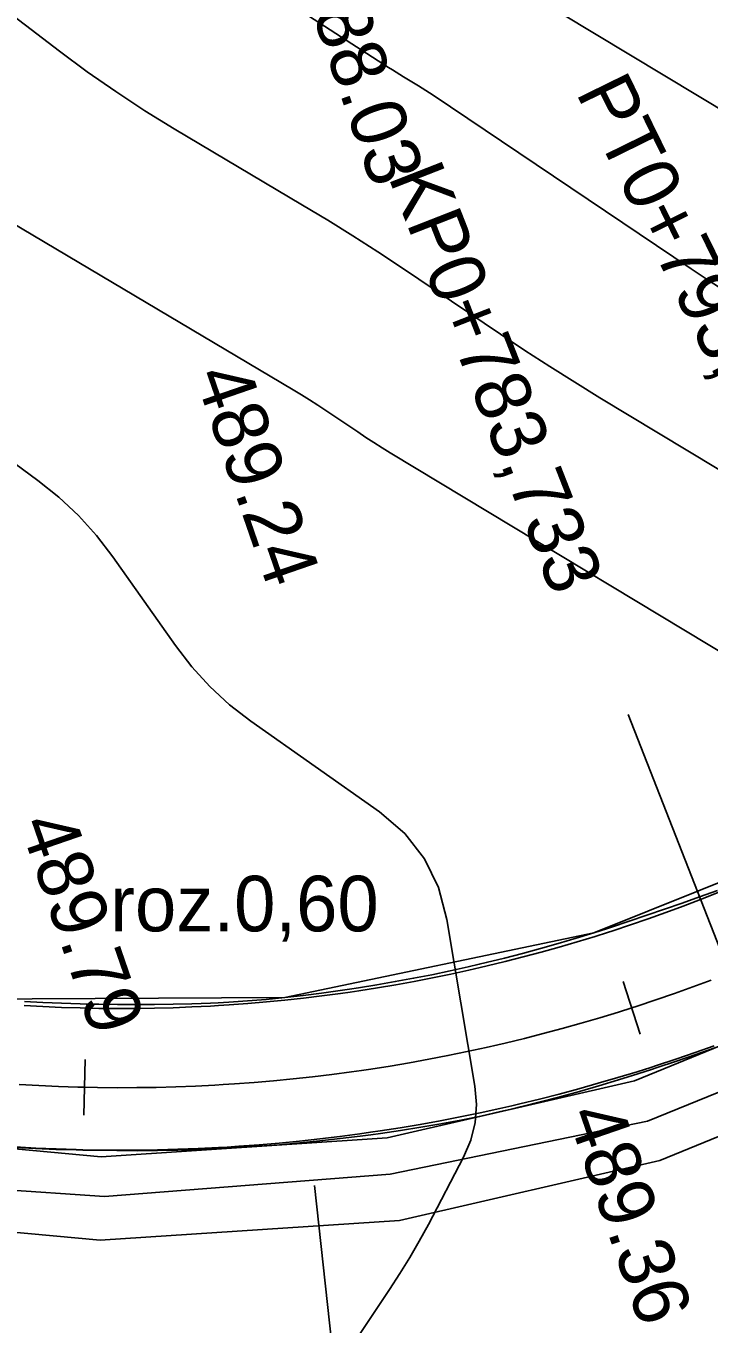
# Model space of a CAD drawing. Extents: x -636600 to -628587, y -1090963 to -1085869.
# Drawn here: x -629074.47 to -629049.89, y -1090800.23 to -1090753.51 of the extents above; entities that cross this region are included whole.
import ezdxf

# ---------------------------------------------------------------- set-up
doc = ezdxf.new("R2010")
doc.units = 0
for name, color, linetype in [('01_PARCELY_NÁVRH_PC', 7, 'Continuous'), ('06_ÚSES_IP_NAVRH', 7, 'Continuous'), ('Ex_Major Contours', 7, 'Continuous'), ('Ex_Minor Contours', 7, 'Continuous'), ('HEKTOMETRY20', 7, 'Continuous'), ('HL_BODY', 7, 'Continuous'), ('koty_vše', 7, 'Continuous'), ('popis', 7, 'Continuous'), ('situace_osa', 7, 'Continuous'), ('situace_těleso', 7, 'Continuous'), ('situace_vozovka', 7, 'Continuous'), ('VRCHOLY', 7, 'Continuous')]:
    doc.layers.add(name, color=color, linetype=linetype)

msp = doc.modelspace()

# ---------------------------------------------------------------- linework, layer by layer
at = {"layer": '01_PARCELY_NÁVRH_PC'}
for points in [[(-629333.446, -1090807.798), (-629185.545, -1090774.978), (-629169.22, -1090774.091), (-629152.689, -1090776.12), (-629083.293, -1090793.147), (-629071.767, -1090794.209), (-629061.471, -1090793.529), (-629052.567, -1090791.475), (-629024.023, -1090779.799), (-629026.589, -1090772.578), (-629040.908, -1090778.632), (-629044.438, -1090782.302), (-629054.034, -1090786.148), (-629065.163, -1090788.479), (-629076.541, -1090788.542), (-629088.985, -1090786.736), (-629149.055, -1090771.958), (-629163.015, -1090769.651), (-629176.084, -1090769.189), (-629189.661, -1090770.446), (-629215.418, -1090775.798)], [(-629332.923, -1090810.755), (-629185.135, -1090777.96), (-629169.323, -1090777.101), (-629153.231, -1090779.076), (-629083.791, -1090796.114), (-629071.806, -1090797.219), (-629061.032, -1090796.507), (-629051.656, -1090794.344), (-629022.513, -1090782.423), (-629023.82, -1090780.369), (-629024.023, -1090779.799), (-629052.567, -1090791.475), (-629061.471, -1090793.529), (-629071.767, -1090794.209), (-629083.293, -1090793.147), (-629152.689, -1090776.12), (-629169.22, -1090774.091), (-629185.545, -1090774.978), (-629333.446, -1090807.798)]]:
    msp.add_lwpolyline(points, dxfattribs=at)
at = {"layer": '06_ÚSES_IP_NAVRH'}
msp.add_lwpolyline([(-629532.12, -1090817.987), (-629446.562, -1090815.158), (-629358.786, -1090812.637), (-629333.428, -1090809.41), (-629185.496, -1090776.496), (-629168.602, -1090775.784), (-629152.436, -1090777.592), (-629083.514, -1090794.829), (-629071.645, -1090795.644), (-629061.361, -1090794.844), (-629052.102, -1090792.936), (-629028.219, -1090783.132)], dxfattribs=at)
at = {"layer": 'Ex_Major Contours'}
msp.add_lwpolyline([(-629056.478, -1090752.283), (-629044.065, -1090759.768)], dxfattribs=at)
at = {"layer": 'Ex_Minor Contours'}
for points in [[(-629049.305, -1090763.06), (-629049.923, -1090762.66), (-629050.536, -1090762.253), (-629059.817, -1090756.004), (-629059.948, -1090755.917), (-629060.08, -1090755.831), (-629060.213, -1090755.748), (-629060.347, -1090755.666), (-629060.887, -1090755.34), (-629061.021, -1090755.259), (-629061.155, -1090755.176), (-629061.288, -1090755.092), (-629061.421, -1090755.007), (-629079.382, -1090743.406)], [(-629082.651, -1090747.242), (-629073.269, -1090754.42), (-629072.267, -1090755.164), (-629071.244, -1090755.878), (-629070.2, -1090756.562), (-629069.136, -1090757.215), (-629064.52, -1090759.958), (-629063.61, -1090760.508), (-629062.708, -1090761.07), (-629061.814, -1090761.644), (-629060.928, -1090762.232), (-629057.4, -1090764.607), (-629056.514, -1090765.196), (-629055.622, -1090765.773), (-629054.722, -1090766.338), (-629053.815, -1090766.893), (-629046.428, -1090771.345)], [(-629046.352, -1090777.92), (-629061.363, -1090768.873), (-629061.659, -1090768.692), (-629061.953, -1090768.507), (-629062.244, -1090768.319), (-629062.533, -1090768.127), (-629063.683, -1090767.353), (-629063.972, -1090767.161), (-629064.264, -1090766.973), (-629064.558, -1090766.79), (-629064.855, -1090766.611), (-629078.698, -1090758.386)], [(-629085.748, -1090761.24), (-629074.048, -1090769.87), (-629073.29, -1090770.476), (-629072.587, -1090771.137), (-629071.941, -1090771.853), (-629071.349, -1090772.623), (-629069.096, -1090775.813), (-629068.503, -1090776.581), (-629067.852, -1090777.29), (-629067.143, -1090777.942), (-629066.375, -1090778.535), (-629061.755, -1090781.801), (-629060.844, -1090782.58), (-629060.135, -1090783.486), (-629059.627, -1090784.519), (-629059.322, -1090785.678), (-629058.32, -1090791.667), (-629058.26, -1090792.332), (-629058.309, -1090792.98), (-629058.464, -1090793.611), (-629058.727, -1090794.225), (-629059.992, -1090796.646), (-629060.317, -1090797.246), (-629060.657, -1090797.838), (-629061.013, -1090798.419), (-629061.385, -1090798.991), (-629064.839, -1090804.149)]]:
    msp.add_lwpolyline(points, dxfattribs=at)
at = {"layer": 'HEKTOMETRY20'}
for points in [[(-629052.976, -1090787.9), (-629052.365, -1090789.805)], [(-629072.349, -1090790.712), (-629072.394, -1090792.711)]]:
    msp.add_lwpolyline(points, dxfattribs=at)
at = {"layer": 'HL_BODY'}
msp.add_lwpolyline([(-629049.155, -1090787.601), (-629052.799, -1090778.289)], dxfattribs=at)
at = {"layer": 'situace_osa'}
msp.add_lwpolyline([(-629074.715, -1090791.613), (-629074.012, -1090791.652), (-629073.307, -1090791.683), (-629072.603, -1090791.706), (-629072.372, -1090791.712), (-629071.898, -1090791.72), (-629071.194, -1090791.727), (-629070.489, -1090791.725), (-629069.784, -1090791.714), (-629069.079, -1090791.696), (-629068.375, -1090791.669), (-629067.671, -1090791.633), (-629067.374, -1090791.616), (-629066.968, -1090791.59), (-629066.265, -1090791.538), (-629065.562, -1090791.478), (-629064.861, -1090791.41), (-629064.16, -1090791.334), (-629063.461, -1090791.249), (-629062.762, -1090791.156), (-629062.402, -1090791.105), (-629062.064, -1090791.055), (-629061.368, -1090790.946), (-629060.673, -1090790.828), (-629059.98, -1090790.703), (-629059.288, -1090790.569), (-629058.597, -1090790.427), (-629057.909, -1090790.277), (-629057.489, -1090790.182), (-629057.222, -1090790.119), (-629056.537, -1090789.953), (-629055.854, -1090789.779), (-629055.173, -1090789.597), (-629054.494, -1090789.406), (-629053.818, -1090789.208), (-629053.144, -1090789.002), (-629052.671, -1090788.853), (-629052.472, -1090788.788), (-629051.803, -1090788.567), (-629051.137, -1090788.337), (-629050.473, -1090788.1), (-629049.812, -1090787.854)], dxfattribs=at)
at = {"layer": 'situace_těleso'}
for points in [[(-629074.531, -1090788.624), (-629073.862, -1090788.66), (-629073.193, -1090788.688), (-629072.524, -1090788.709), (-629072.304, -1090788.714), (-629071.854, -1090788.722), (-629071.185, -1090788.731), (-629070.515, -1090788.736), (-629069.845, -1090788.733), (-629069.176, -1090788.723), (-629068.506, -1090788.705), (-629067.836, -1090788.679), (-629067.554, -1090788.666), (-629067.167, -1090788.645), (-629066.498, -1090788.604), (-629065.83, -1090788.546), (-629065.163, -1090788.479), (-629064.497, -1090788.404), (-629063.832, -1090788.32), (-629063.169, -1090788.23), (-629062.826, -1090788.18), (-629062.506, -1090788.131), (-629061.844, -1090788.024), (-629061.184, -1090787.91), (-629060.525, -1090787.788), (-629059.868, -1090787.659), (-629059.212, -1090787.521), (-629058.558, -1090787.376), (-629058.16, -1090787.284), (-629057.906, -1090787.223), (-629057.255, -1090787.063), (-629056.607, -1090786.895), (-629055.961, -1090786.72), (-629055.316, -1090786.537), (-629054.674, -1090786.346), (-629054.034, -1090786.148), (-629053.585, -1090786.005), (-629053.397, -1090785.943), (-629052.761, -1090785.733), (-629052.126, -1090785.519), (-629051.493, -1090785.302), (-629050.86, -1090785.081), (-629050.229, -1090784.856), (-629049.589, -1090784.624)], [(-629049.675, -1090790.288), (-629050.367, -1090790.53), (-629051.059, -1090790.766), (-629051.754, -1090790.999), (-629051.959, -1090791.067), (-629052.45, -1090791.226), (-629053.148, -1090791.445), (-629053.85, -1090791.656), (-629054.553, -1090791.859), (-629055.259, -1090792.054), (-629055.968, -1090792.24), (-629056.678, -1090792.418), (-629056.956, -1090792.485), (-629057.391, -1090792.588), (-629058.106, -1090792.749), (-629058.824, -1090792.895), (-629059.545, -1090793.027), (-629060.267, -1090793.15), (-629060.99, -1090793.265), (-629061.715, -1090793.371), (-629062.066, -1090793.419), (-629062.441, -1090793.469), (-629063.167, -1090793.559), (-629063.895, -1090793.64), (-629064.623, -1090793.713), (-629065.353, -1090793.778), (-629066.082, -1090793.834), (-629066.813, -1090793.882), (-629067.235, -1090793.905), (-629067.543, -1090793.921), (-629068.274, -1090793.952), (-629069.006, -1090793.974), (-629069.737, -1090793.988), (-629070.469, -1090793.994), (-629071.2, -1090793.991), (-629071.931, -1090793.98), (-629072.423, -1090793.973), (-629072.663, -1090793.968), (-629073.394, -1090793.949), (-629074.125, -1090793.92), (-629074.855, -1090793.884)]]:
    msp.add_lwpolyline(points, dxfattribs=at)
at = {"layer": 'situace_vozovka'}
for points in [[(-629074.54, -1090788.768), (-629073.869, -1090788.806), (-629073.199, -1090788.835), (-629072.528, -1090788.857), (-629072.307, -1090788.862), (-629071.857, -1090788.871), (-629071.185, -1090788.877), (-629070.514, -1090788.875), (-629069.843, -1090788.865), (-629069.172, -1090788.847), (-629068.501, -1090788.821), (-629067.83, -1090788.788), (-629067.547, -1090788.771), (-629067.16, -1090788.746), (-629066.491, -1090788.697), (-629065.822, -1090788.64), (-629065.153, -1090788.575), (-629064.486, -1090788.502), (-629063.82, -1090788.422), (-629063.154, -1090788.333), (-629062.811, -1090788.284), (-629062.49, -1090788.237), (-629061.827, -1090788.133), (-629061.165, -1090788.021), (-629060.504, -1090787.901), (-629059.845, -1090787.774), (-629059.187, -1090787.639), (-629058.531, -1090787.496), (-629058.132, -1090787.405), (-629057.877, -1090787.345), (-629057.225, -1090787.187), (-629056.574, -1090787.021), (-629055.926, -1090786.848), (-629055.279, -1090786.667), (-629054.635, -1090786.478), (-629053.993, -1090786.282), (-629053.542, -1090786.139), (-629053.353, -1090786.078), (-629052.716, -1090785.867), (-629052.081, -1090785.648), (-629051.449, -1090785.422), (-629050.82, -1090785.188), (-629050.193, -1090784.947), (-629049.56, -1090784.695)], [(-629074.854, -1090793.859), (-629074.124, -1090793.899), (-629073.393, -1090793.932), (-629072.662, -1090793.955), (-629072.422, -1090793.961), (-629071.931, -1090793.97), (-629071.2, -1090793.977), (-629070.469, -1090793.974), (-629069.738, -1090793.964), (-629069.007, -1090793.944), (-629068.276, -1090793.916), (-629067.546, -1090793.88), (-629067.237, -1090793.862), (-629066.816, -1090793.835), (-629066.086, -1090793.781), (-629065.358, -1090793.719), (-629064.63, -1090793.648), (-629063.903, -1090793.569), (-629063.177, -1090793.481), (-629062.452, -1090793.385), (-629062.079, -1090793.332), (-629061.729, -1090793.28), (-629061.006, -1090793.166), (-629060.285, -1090793.045), (-629059.566, -1090792.914), (-629058.848, -1090792.775), (-629058.131, -1090792.628), (-629057.417, -1090792.473), (-629056.982, -1090792.374), (-629056.704, -1090792.309), (-629055.994, -1090792.136), (-629055.285, -1090791.956), (-629054.579, -1090791.767), (-629053.874, -1090791.569), (-629053.173, -1090791.364), (-629052.473, -1090791.15), (-629051.983, -1090790.995), (-629051.777, -1090790.928), (-629051.083, -1090790.698), (-629050.391, -1090790.46), (-629049.703, -1090790.214)]]:
    msp.add_lwpolyline(points, dxfattribs=at)
at = {"layer": 'VRCHOLY'}
msp.add_lwpolyline([(-629064.088, -1090795.241), (-629061.919, -1090815.123)], dxfattribs=at)

# ---------------------------------------------------------------- texts
at = {"layer": 'HL_BODY'}
for s, rotation, p in [('PT0+793,733', 296.1455, (-629054.699, -1090755.898)), ('KP0+783,733', 291.3708, (-629061.448, -1090758.93))]:
    msp.add_text(s, height=2, rotation=rotation, dxfattribs=at).set_placement(p)
at = {"layer": 'koty_vše'}
for s, p in [('488.03', (-629064.655, -1090751.681)), ('489.24', (-629068.421, -1090766.086)), ('489.79', (-629074.72, -1090782.227)), ('489.36', (-629055.01, -1090792.681))]:
    msp.add_text(s, height=2, rotation=289.043, dxfattribs=at).set_placement(p)
at = {"layer": 'popis'}
msp.add_text('roz.0,60', height=2, dxfattribs=at).set_placement((-629071.441, -1090786.099))

doc.saveas('drawing.dxf')
